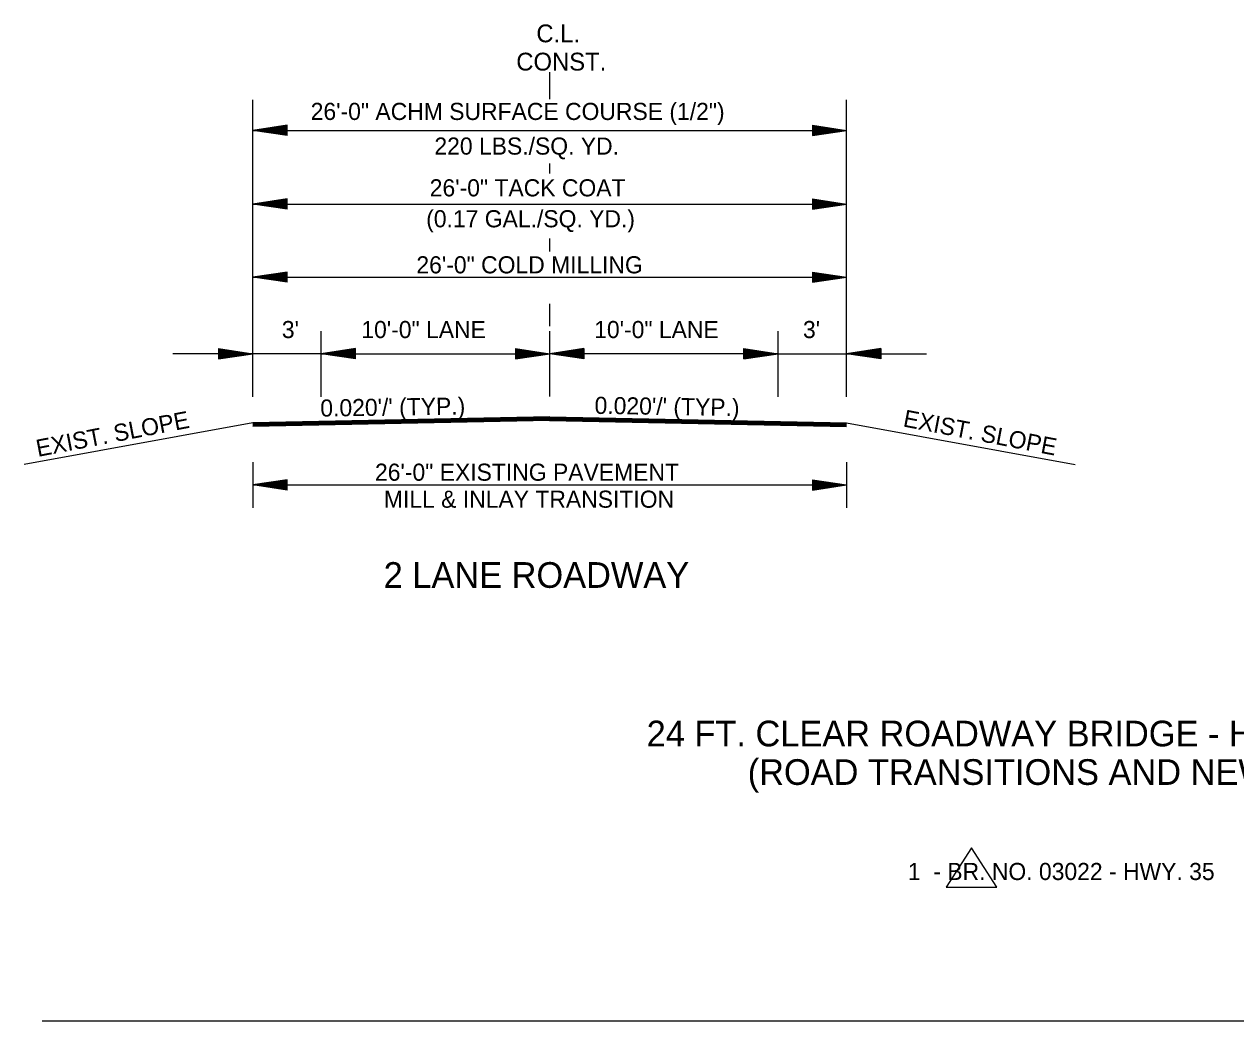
# Model space of a CAD drawing. Extents: x 544259 to 1930787, y -1961343 to 596640.
# Drawn here: x 544259 to 544789, y -1949124 to -1948688 of the extents above; entities that cross this region are included whole.
import ezdxf

# ---------------------------------------------------------------- set-up
doc = ezdxf.new("R2010")
doc.units = 0
doc.layers.add('R_Border', color=7, linetype='Continuous')
doc.layers.add('R_Draft', color=7, linetype='Continuous')

msp = doc.modelspace()

# ---------------------------------------------------------------- linework, layer by layer
at = {"layer": 'R_Border'}
for p, q in [((544673.69, -1949048.46), (544662.65, -1949065.76)), ((544684.73, -1949065.76), (544673.69, -1949048.46)), ((544662.65, -1949065.76), (544684.73, -1949065.76)), ((544266.84, -1949124.25), (545225.68, -1949124.25))]:
    msp.add_line(p, q, dxfattribs=at)
at = {"layer": 'R_Draft'}
for p, q in [((544489.03, -1948720.53), (544489.03, -1948708.74)), ((544359.03, -1948850.9), (544359.03, -1948720.84)), ((544619.03, -1948850.9), (544619.03, -1948720.84)), ((544374.03, -1948731.96), (544359.03, -1948734.21)), ((544374.03, -1948732.33), (544361.54, -1948734.21)), ((544374.03, -1948732.71), (544364.12, -1948734.21)), ((544374.03, -1948733.09), (544366.62, -1948734.21)), ((544374.03, -1948733.47), (544369.16, -1948734.21)), ((544374.03, -1948736.46), (544374.03, -1948731.96)), ((544604.03, -1948731.96), (544619.03, -1948734.21)), ((544604.03, -1948731.96), (544604.03, -1948736.46)), ((544604.03, -1948732.33), (544616.53, -1948734.21)), ((544604.03, -1948732.71), (544613.95, -1948734.21)), ((544604.03, -1948733.09), (544611.45, -1948734.21)), ((544604.03, -1948733.48), (544608.91, -1948734.21)), ((544359.03, -1948734.21), (544619.03, -1948734.21)), ((544374.03, -1948736.46), (544359.03, -1948734.21)), ((544374.03, -1948736.08), (544361.54, -1948734.21)), ((544374.03, -1948735.7), (544364.12, -1948734.21)), ((544374.03, -1948735.32), (544366.62, -1948734.21)), ((544374.03, -1948734.93), (544369.16, -1948734.21)), ((544374.03, -1948733.85), (544371.66, -1948734.21)), ((544374.03, -1948734.56), (544371.66, -1948734.21)), ((544604.03, -1948733.85), (544606.4, -1948734.21)), ((544604.03, -1948736.46), (544619.03, -1948734.21)), ((544604.03, -1948734.94), (544608.91, -1948734.21)), ((544604.03, -1948735.7), (544613.95, -1948734.21)), ((544604.03, -1948736.08), (544616.53, -1948734.21)), ((544604.03, -1948735.32), (544611.45, -1948734.21)), ((544604.03, -1948734.56), (544606.4, -1948734.21)), ((544489.03, -1948753.12), (544489.03, -1948748.72)), ((544374.03, -1948764.23), (544359.03, -1948766.48)), ((544374.03, -1948764.61), (544361.54, -1948766.48)), ((544374.03, -1948764.99), (544364.12, -1948766.48)), ((544374.03, -1948768.73), (544374.03, -1948764.23)), ((544604.03, -1948764.23), (544619.03, -1948766.48)), ((544604.03, -1948764.23), (544604.03, -1948768.73)), ((544604.03, -1948764.61), (544616.53, -1948766.48)), ((544604.03, -1948764.99), (544613.95, -1948766.48)), ((544359.03, -1948766.48), (544619.03, -1948766.48)), ((544374.03, -1948768.73), (544359.03, -1948766.48)), ((544374.03, -1948768.36), (544361.54, -1948766.48)), ((544374.03, -1948767.97), (544364.12, -1948766.48)), ((544374.03, -1948765.36), (544366.62, -1948766.48)), ((544374.03, -1948767.6), (544366.62, -1948766.48)), ((544374.03, -1948765.75), (544369.16, -1948766.48)), ((544374.03, -1948767.21), (544369.16, -1948766.48)), ((544374.03, -1948766.13), (544371.66, -1948766.48)), ((544374.03, -1948766.83), (544371.66, -1948766.48)), ((544604.03, -1948765.36), (544611.45, -1948766.48)), ((544604.03, -1948765.75), (544608.91, -1948766.48)), ((544604.03, -1948766.13), (544606.4, -1948766.48)), ((544604.03, -1948768.73), (544619.03, -1948766.48)), ((544604.03, -1948767.22), (544608.91, -1948766.48)), ((544604.03, -1948767.97), (544613.95, -1948766.48)), ((544604.03, -1948768.36), (544616.53, -1948766.48)), ((544604.03, -1948767.6), (544611.45, -1948766.48)), ((544604.03, -1948766.83), (544606.4, -1948766.48)), ((544489.03, -1948787.25), (544489.03, -1948781.65)), ((544374.03, -1948796.28), (544359.03, -1948798.53)), ((544374.03, -1948796.66), (544361.54, -1948798.53)), ((544374.03, -1948797.04), (544364.12, -1948798.53)), ((544374.03, -1948800.78), (544374.03, -1948796.28)), ((544604.03, -1948796.28), (544619.03, -1948798.53)), ((544604.03, -1948796.28), (544604.03, -1948800.78)), ((544604.03, -1948796.66), (544616.53, -1948798.53)), ((544604.03, -1948797.04), (544613.95, -1948798.53)), ((544359.03, -1948798.53), (544619.03, -1948798.53)), ((544374.03, -1948800.78), (544359.03, -1948798.53)), ((544374.03, -1948800.41), (544361.54, -1948798.53)), ((544374.03, -1948800.03), (544364.12, -1948798.53)), ((544374.03, -1948797.42), (544366.62, -1948798.53)), ((544374.03, -1948799.65), (544366.62, -1948798.53)), ((544374.03, -1948797.8), (544369.16, -1948798.53)), ((544374.03, -1948799.26), (544369.16, -1948798.53)), ((544374.03, -1948798.18), (544371.66, -1948798.53)), ((544374.03, -1948798.89), (544371.66, -1948798.53)), ((544604.03, -1948797.42), (544611.45, -1948798.53)), ((544604.03, -1948797.81), (544608.91, -1948798.53)), ((544604.03, -1948798.18), (544606.4, -1948798.53)), ((544604.03, -1948800.78), (544619.03, -1948798.53)), ((544604.03, -1948799.27), (544608.91, -1948798.53)), ((544604.03, -1948800.03), (544613.95, -1948798.53)), ((544604.03, -1948800.41), (544616.53, -1948798.53)), ((544604.03, -1948799.65), (544611.45, -1948798.53)), ((544604.03, -1948798.89), (544606.4, -1948798.53)), ((544489.03, -1948820.05), (544489.03, -1948810.18)), ((544389.03, -1948850.9), (544389.03, -1948822.18)), ((544489.03, -1948850.73), (544489.03, -1948822.18)), ((544589.03, -1948850.9), (544589.03, -1948822.18)), ((544389.03, -1948832.07), (544324.03, -1948832.07)), ((544344.03, -1948829.82), (544359.03, -1948832.07)), ((544344.03, -1948829.82), (544344.03, -1948834.32)), ((544344.03, -1948830.2), (544356.53, -1948832.07)), ((544344.03, -1948830.58), (544353.95, -1948832.07)), ((544344.03, -1948830.95), (544351.45, -1948832.07)), ((544344.03, -1948831.34), (544348.91, -1948832.07)), ((544344.03, -1948831.72), (544346.4, -1948832.07)), ((544344.03, -1948834.32), (544359.03, -1948832.07)), ((544344.03, -1948832.81), (544348.91, -1948832.07)), ((544344.03, -1948833.56), (544353.95, -1948832.07)), ((544344.03, -1948833.95), (544356.53, -1948832.07)), ((544344.03, -1948833.19), (544351.45, -1948832.07)), ((544344.03, -1948832.42), (544346.4, -1948832.07)), ((544404.03, -1948829.82), (544389.03, -1948832.07)), ((544404.03, -1948834.32), (544389.03, -1948832.07)), ((544389.03, -1948832.07), (544489.03, -1948832.07)), ((544404.03, -1948830.2), (544391.54, -1948832.07)), ((544404.03, -1948833.95), (544391.54, -1948832.07)), ((544404.03, -1948830.58), (544394.12, -1948832.07)), ((544404.03, -1948833.56), (544394.12, -1948832.07)), ((544404.03, -1948830.95), (544396.62, -1948832.07)), ((544404.03, -1948833.19), (544396.62, -1948832.07)), ((544404.03, -1948831.34), (544399.16, -1948832.07)), ((544404.03, -1948832.8), (544399.16, -1948832.07)), ((544404.03, -1948831.72), (544401.66, -1948832.07)), ((544404.03, -1948832.42), (544401.66, -1948832.07)), ((544404.03, -1948834.32), (544404.03, -1948829.82)), ((544474.03, -1948829.82), (544489.03, -1948832.07)), ((544474.03, -1948829.82), (544474.03, -1948834.32)), ((544474.03, -1948830.2), (544486.53, -1948832.07)), ((544474.03, -1948830.58), (544483.95, -1948832.07)), ((544474.03, -1948830.95), (544481.45, -1948832.07)), ((544474.03, -1948831.34), (544478.91, -1948832.07)), ((544474.03, -1948831.72), (544476.4, -1948832.07)), ((544474.03, -1948834.32), (544489.03, -1948832.07)), ((544474.03, -1948832.81), (544478.91, -1948832.07)), ((544474.03, -1948833.56), (544483.95, -1948832.07)), ((544474.03, -1948833.95), (544486.53, -1948832.07)), ((544474.03, -1948833.19), (544481.45, -1948832.07)), ((544474.03, -1948832.42), (544476.4, -1948832.07)), ((544504.03, -1948829.82), (544489.03, -1948832.07)), ((544589.03, -1948832.07), (544489.03, -1948832.07)), ((544504.03, -1948834.32), (544489.03, -1948832.07)), ((544504.03, -1948830.2), (544491.54, -1948832.07)), ((544504.03, -1948833.95), (544491.54, -1948832.07)), ((544504.03, -1948830.58), (544494.12, -1948832.07)), ((544504.03, -1948833.56), (544494.12, -1948832.07)), ((544504.03, -1948830.95), (544496.62, -1948832.07)), ((544504.03, -1948833.19), (544496.62, -1948832.07)), ((544504.03, -1948831.34), (544499.16, -1948832.07)), ((544504.03, -1948832.81), (544499.16, -1948832.07)), ((544504.03, -1948831.72), (544501.66, -1948832.07)), ((544504.03, -1948832.42), (544501.66, -1948832.07)), ((544504.03, -1948829.82), (544504.03, -1948834.32)), ((544574.03, -1948829.82), (544589.03, -1948832.07)), ((544574.03, -1948834.32), (544574.03, -1948829.82)), ((544574.03, -1948830.2), (544586.53, -1948832.07)), ((544574.03, -1948830.58), (544583.95, -1948832.07)), ((544574.03, -1948830.95), (544581.45, -1948832.07)), ((544574.03, -1948831.34), (544578.91, -1948832.07)), ((544574.03, -1948831.72), (544576.4, -1948832.07)), ((544574.03, -1948834.32), (544589.03, -1948832.07)), ((544574.03, -1948832.8), (544578.91, -1948832.07)), ((544574.03, -1948833.56), (544583.95, -1948832.07)), ((544574.03, -1948833.95), (544586.53, -1948832.07)), ((544574.03, -1948833.19), (544581.45, -1948832.07)), ((544574.03, -1948832.42), (544576.4, -1948832.07)), ((544589.03, -1948832.07), (544654.03, -1948832.07)), ((544634.03, -1948829.82), (544619.03, -1948832.07)), ((544634.03, -1948834.32), (544619.03, -1948832.07)), ((544634.03, -1948830.2), (544621.54, -1948832.07)), ((544634.03, -1948833.95), (544621.54, -1948832.07)), ((544634.03, -1948830.58), (544624.12, -1948832.07)), ((544634.03, -1948833.56), (544624.12, -1948832.07)), ((544634.03, -1948830.95), (544626.62, -1948832.07)), ((544634.03, -1948833.19), (544626.62, -1948832.07)), ((544634.03, -1948831.34), (544629.16, -1948832.07)), ((544634.03, -1948832.81), (544629.16, -1948832.07)), ((544634.03, -1948831.72), (544631.66, -1948832.07)), ((544634.03, -1948832.42), (544631.66, -1948832.07)), ((544634.03, -1948829.82), (544634.03, -1948834.32)), ((544489.03, -1948859.68), (544359.03, -1948862.28)), ((544489.04, -1948859.98), (544359.03, -1948862.58)), ((544489.04, -1948860.28), (544359.03, -1948862.88)), ((544489.05, -1948860.58), (544359.03, -1948863.18)), ((544489.01, -1948860.58), (544619.03, -1948863.18)), ((544489.02, -1948860.28), (544619.03, -1948862.88)), ((544489.03, -1948859.68), (544619.03, -1948862.28)), ((544489.03, -1948859.98), (544619.03, -1948862.58)), ((544359.03, -1948862.28), (544258.96, -1948880.65)), ((544489.06, -1948860.88), (544359.03, -1948863.48)), ((544489.06, -1948861.18), (544359.03, -1948863.78)), ((544489.07, -1948861.35), (544359.03, -1948863.95)), ((544489, -1948861.18), (544619.03, -1948863.78)), ((544489, -1948861.35), (544619.03, -1948863.95)), ((544489.01, -1948860.88), (544619.03, -1948863.48)), ((544619.03, -1948862.28), (544719.1, -1948880.65)), ((544359.03, -1948879.53), (544359.03, -1948899.53)), ((544619.03, -1948879.53), (544619.03, -1948899.53)), ((544374.03, -1948887.28), (544359.03, -1948889.53)), ((544374.03, -1948891.78), (544374.03, -1948887.28)), ((544604.03, -1948887.28), (544619.03, -1948889.53)), ((544604.03, -1948887.28), (544604.03, -1948891.78)), ((544359.03, -1948889.53), (544619.03, -1948889.53)), ((544374.03, -1948891.78), (544359.03, -1948889.53)), ((544374.03, -1948887.66), (544361.54, -1948889.53)), ((544374.03, -1948891.41), (544361.54, -1948889.53)), ((544374.03, -1948888.04), (544364.12, -1948889.53)), ((544374.03, -1948891.03), (544364.12, -1948889.53)), ((544374.03, -1948888.42), (544366.62, -1948889.53)), ((544374.03, -1948890.65), (544366.62, -1948889.53)), ((544374.03, -1948888.8), (544369.16, -1948889.53)), ((544374.03, -1948890.26), (544369.16, -1948889.53)), ((544374.03, -1948889.18), (544371.66, -1948889.53)), ((544374.03, -1948889.89), (544371.66, -1948889.53)), ((544604.03, -1948887.66), (544616.53, -1948889.53)), ((544604.03, -1948888.04), (544613.95, -1948889.53)), ((544604.03, -1948888.42), (544611.45, -1948889.53)), ((544604.03, -1948888.81), (544608.91, -1948889.53)), ((544604.03, -1948889.18), (544606.4, -1948889.53)), ((544604.03, -1948891.78), (544619.03, -1948889.53)), ((544604.03, -1948890.27), (544608.91, -1948889.53)), ((544604.03, -1948891.03), (544613.95, -1948889.53)), ((544604.03, -1948891.41), (544616.53, -1948889.53)), ((544604.03, -1948890.65), (544611.45, -1948889.53)), ((544604.03, -1948889.89), (544606.4, -1948889.53))]:
    msp.add_line(p, q, dxfattribs=at)

# ---------------------------------------------------------------- texts
for s, height, p in [('C.L.', 7.8, (544483.19, -1948695.64)), ('CONST.', 7.8, (544474.4, -1948708.01)), ('26\'-0" ACHM SURFACE COURSE (1/2")', 7.5, (544384.38, -1948729.67)), ('220 LBS./SQ. YD. ', 7.5, (544438.54, -1948744.85)), ('26\'-0" TACK COAT', 7.5, (544436.5, -1948763.14)), ('(0.17 GAL./SQ. YD.)', 7.5, (544434.95, -1948776.69)), ('26\'-0" COLD MILLING', 7.5, (544430.66, -1948796.86)), ("3'", 7.5, (544371.76, -1948825.21)), ('10\'-0" LANE', 7.5, (544406.55, -1948825.21)), ('10\'-0" LANE', 7.5, (544508.5, -1948825.21)), ("3'", 7.5, (544599.92, -1948825.21)), ('26\'-0" EXISTING PAVEMENT', 7.5, (544412.53, -1948887.7)), ('MILL & INLAY TRANSITION ', 7.5, (544416.42, -1948899.53)), ('2 LANE ROADWAY', 11.25, (544416.34, -1948934.61)), ('24 FT. CLEAR ROADWAY BRIDGE - HYDRODEMOLITION', 11.25, (544531.47, -1949004.05)), ('(ROAD TRANSITIONS AND NEW GUARDRAIL)', 11.25, (544575.72, -1949020.92)), ('      1  - BR. NO. 03022 - HWY. 35', 7.5, (544629.11, -1949062.6))]:
    msp.add_text(s, height=height, dxfattribs=at).set_placement(p)
for s, rotation, p in [("0.020'/' (TYP.)", 0.8719, (544388.65, -1948859.63)), ("0.020'/' (TYP.)", 359.1281, (544508.63, -1948858.4)), ('EXIST. SLOPE', 10.8829, (544264.94, -1948877.27)), ('EXIST. SLOPE', 349.1171, (544643.41, -1948863.87))]:
    msp.add_text(s, height=7.5, rotation=rotation, dxfattribs=at).set_placement(p)

doc.saveas('drawing.dxf')
